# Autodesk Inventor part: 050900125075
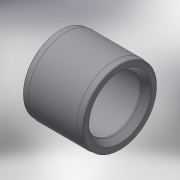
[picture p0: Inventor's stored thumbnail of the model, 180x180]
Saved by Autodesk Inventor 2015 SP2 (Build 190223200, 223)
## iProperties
Created: 2017-11
Part Number: 050900125075
Material: Generic
Description: PLASSON BUSHING-CEMENT PVC 125-75
Document SubType Name: Modeling
Designer: KIM
Density: 1 g/cm^3
Appearance: Default
Author: KIM
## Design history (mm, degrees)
derived "050900.ipt"
feature "Solid1::050900.ipt"
tag "TaggingFeature1"
body "Solid1"
other parameters: "d0" = 75, "d1" = 125, "d2" = 44, "d3" = 69, "d7" = 6.9, "d11" = 6.9, "d12" = 1.25, "d14" = 1.25, "d15" = 6.9, "d17" = 1.25, "d18" = 1.25, "d19" = 66.75, "d20" = 5, "d21" = 17.475, "D_" = 125, "d_" = 75, "L_" = 69, "l_" = 44, "z_" = 2
